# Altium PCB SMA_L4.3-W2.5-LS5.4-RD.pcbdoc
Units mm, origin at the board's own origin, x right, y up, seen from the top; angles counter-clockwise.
Board outline 18.9 x 15.5 mm, 2 copper layers (Top Layer, Bottom Layer), stack 0 mm thick; 1 components, 0 nets, 2 pads, 0 vias.
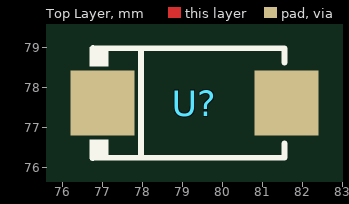
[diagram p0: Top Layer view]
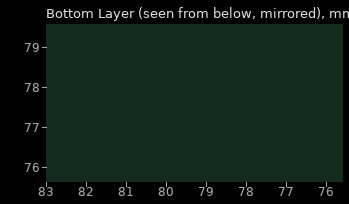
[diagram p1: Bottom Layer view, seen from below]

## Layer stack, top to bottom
Top Layer: signal copper (thickness not stored)
Bottom Layer: signal copper (thickness not stored)

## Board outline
88.75,69.85 69.85,69.85 69.85,85.35 88.75,85.35

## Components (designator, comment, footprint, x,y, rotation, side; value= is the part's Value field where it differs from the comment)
U? "" SMA_L4.3-W2.5-LS5.4-RD 79.3,77.6 r0 top

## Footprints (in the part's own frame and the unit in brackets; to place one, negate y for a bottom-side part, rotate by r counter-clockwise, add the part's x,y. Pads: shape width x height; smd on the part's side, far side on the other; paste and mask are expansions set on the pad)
SMA_L4.3-W2.5-LS5.4-RD [mm]
  rect 1.6x1.62 smd: 1(-2.3,0) 2(2.3,0)
  silkscreen extent -2.62,-1.4 2.25,1.4

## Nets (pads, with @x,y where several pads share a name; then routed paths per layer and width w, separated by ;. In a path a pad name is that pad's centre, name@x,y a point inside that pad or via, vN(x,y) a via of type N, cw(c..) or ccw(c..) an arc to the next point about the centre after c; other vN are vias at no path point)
pads on no net: U?.1 U?.2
